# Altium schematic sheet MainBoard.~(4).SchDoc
size A4
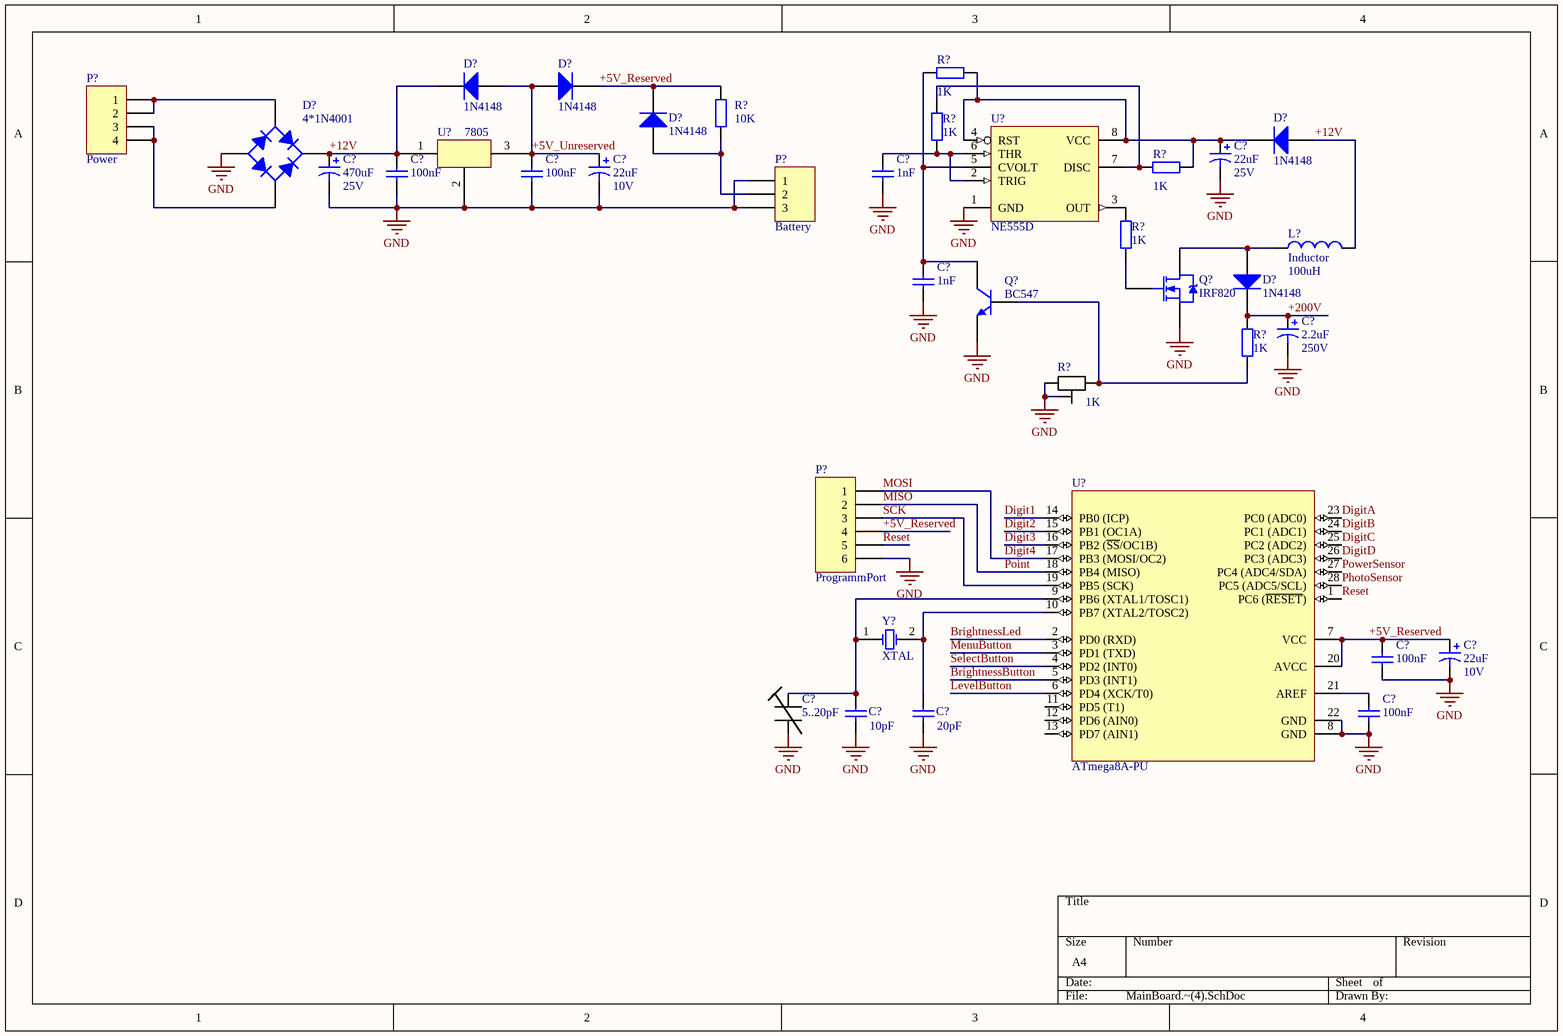
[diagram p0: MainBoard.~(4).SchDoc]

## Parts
(Parts that share a designator on the sheet are numbered #1, #2 ... from top to bottom, then left to right.)
C?#1  25V  value 22uF  [RB7.6-15]
C?#2  25V  value 470uF  [RB7.6-15]
C?#3  10V  value 22uF  [RB7.6-15]
C?#4  value 100nF  [RAD-0.3]  (hidden comment: Cap)
C?#5  value 100nF  [RAD-0.3]  (hidden comment: Cap)
C?#6  value 1nF  [RAD-0.3]  (hidden comment: Cap)
C?#7  value 1nF  [RAD-0.3]  (hidden comment: Cap)
C?#8  250V  value 2.2uF  [RB7.6-15]
C?#9  10V  value 22uF  [RB7.6-15]
C?#10  value 100nF  [RAD-0.3]  (hidden comment: Cap)
C?#11  5..20pF
C?#12  value 10pF  [RAD-0.3]  (hidden comment: Cap)
C?#13  value 20pF  [RAD-0.3]  (hidden comment: Cap)
C?#14  value 100nF  [RAD-0.3]  (hidden comment: Cap)
D?#1  1N4148  [DO-35]
D?#2  1N4148  [DO-35]
D?#3  4*1N4001  [D-38]
D?#4  1N4148  [DO-35]
D?#5  1N4148  [DO-35]
D?#6  1N4148  [DO-35]
L?  Inductor  value 100uH  [0402-A]
P?#1  Power  [HDR1X4]
P?#2  Battery  [HDR1X3]
P?#3  ProgrammPort  [HDR1X6]
Q?#1  IRF820  [TO-220AB]
Q?#2  BC547  [TO-92A]
R?#1  value 1K  [AXIAL-0.4]  (hidden comment: Res2)
R?#2  value 10K  [AXIAL-0.4]  (hidden comment: Res2)
R?#3  value 1K  [AXIAL-0.4]  (hidden comment: Res2)
R?#4  value 1K  [AXIAL-0.4]  (hidden comment: Res2)
R?#5  value 1K  [AXIAL-0.4]  (hidden comment: Res2)
R?#6  value 1K  [AXIAL-0.4]  (hidden comment: Res2)
R?#7  1K
U?#1  NE555D  [D008_N]
U?#2  7805
U?#3  ATmega8A-PU  [28P3]
Y?  XTAL  [R38]

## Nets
GND: C?#1.2 C?#2.2 C?#3.2 C?#4.1 C?#5.1 C?#6.1 C?#7.1 C?#8.2 C?#9.2 C?#10.1 C?#11.1 C?#12.1 C?#13.1 C?#14.1 D?#3.3(A) P?#2.1 P?#2.3 P?#3.6 Q?#1.3(S) Q?#2.1(E) R?#7.2 R?#7.3 U?#1.1(GND) U?#2.2(GND) U?#3.8(GND) U?#3.22(GND)
+5V_Reserved: C?#9.1 C?#10.2 D?#2.2(K) D?#4.2(K) P?#3.4 R?#2.2 U?#3.7(VCC) U?#3.20(AVCC)
+5V_Unreserved: C?#3.1 C?#5.2 D?#1.1(A) D?#2.1(A) U?#2.3(Out)
+12V: C?#2.1 C?#4.2 D?#1.2(K) D?#3.1(K) D?#5.1(A) L?.2 U?#2.1(In)
+200V: C?#8.1 D?#6.2(K) R?#6.2
BrightnessButton: U?#3.5(PD3_(INT1))
BrightnessLed: U?#3.2(PD0_(RXD))
Digit1: U?#3.14(PB0_(ICP))
Digit2: U?#3.15(PB1_(OC1A))
Digit3: U?#3.16(PB2_(~{SS}/OC1B))
Digit4: P?#3.1 U?#3.17(PB3_(MOSI/OC2))  [also labelled MOSI]
DigitA: U?#3.23(PC0_(ADC0))
DigitB: U?#3.24(PC1_(ADC1))
DigitC: U?#3.25(PC2_(ADC2))
DigitD: U?#3.26(PC3_(ADC3))
LevelButton: U?#3.6(PD4_(XCK/T0))
MenuButton: U?#3.3(PD1_(TXD))
MISO: P?#3.2 U?#3.18(PB4_(MISO))  [also labelled Point]
PhotoSensor: U?#3.28(PC5_(ADC5/SCL))
PowerSensor: U?#3.27(PC4_(ADC4/SDA))
Reset: P?#3.5 U?#3.1(PC6_(~{RESET}))
SCK: P?#3.3 U?#3.19(PB5_(SCK))
SelectButton: U?#3.4(PD2_(INT0))
NetC?#1_1: C?#1.1 D?#5.2(K) R?#1.2 R?#4.2 U?#1.4(RST) U?#1.8(VCC)
NetC?#6_2: C?#6.2 R?#3.1 U?#1.2(TRIG) U?#1.6(THR)
NetC?#7_2: C?#7.2 Q?#2.3(C) R?#1.1 U?#1.5(CVOLT)
NetC?#11_2: C?#11.2 C?#12.2 U?#3.9(PB6_(XTAL1/TOSC1)) Y?.1(OSC1)
NetC?#13_2: C?#13.2 U?#3.10(PB7_(XTAL2/TOSC2)) Y?.2(OSC2)
NetC?#14_2: C?#14.2 U?#3.21(AREF)
NetD?#3_2: D?#3.2(C) P?#1.3 P?#1.4
NetD?#3_4: D?#3.4(C) P?#1.1 P?#1.2
NetD?#4_1: D?#4.1(A) P?#2.2 R?#2.1
NetD?#6_1: D?#6.1(A) L?.1 Q?#1.2(D)
NetQ?#1_1: Q?#1.1(G) R?#5.1
NetQ?#2_2: Q?#2.2(B) R?#6.1 R?#7.1
NetR?#3_2: R?#3.2 R?#4.1 U?#1.7(DISC)
NetR?#5_2: R?#5.2 U?#1.3(OUT)

Not connected (* = marked no-connect by the designer): U?#3 11(PD5_(T1)) 12(PD6_(AIN0)) 13(PD7_(AIN1))

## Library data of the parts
C?#1-C?#3 C?#8 C?#9 = Cap Pol1: Polarized Capacitor (Radial)
C?#4-C?#7 C?#10 C?#12-C?#14 = Cap: Capacitor
C?#11 = Trimmer_cap
D?#1 D?#2 D?#4-D?#6 = Diode 1N4148: High Conductance Fast Diode
D?#3 = Bridge1: Full Wave Diode Bridge
L? = Inductor: Code_IEC: 1005
P?#1 = Header 4: Header, 4-Pin
P?#2 = Header 3: Header, 3-Pin
P?#3 = Header 6: Header, 6-Pin
Q?#1 = IRF820: HEXFET N-Channel Power MOSFET; Note: Pin 2 is electrically connected to pin 4.
Q?#2 = 2N3904: NPN General Purpose Amplifier
R?#1-R?#6 = Res2: Resistor
R?#7 = Trimmer_res
U?#1 = NE555D: Precision Timer
U?#3 = ATmega8A-PU: 8-bit AVR Microcontroller, 8KB Flash, 512 Bytes EEPROM, 1KB SRAM, 28-pin PDIP, Industrial Grade (-40°C to 85°C)
Y? = XTAL: Crystal Oscillator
